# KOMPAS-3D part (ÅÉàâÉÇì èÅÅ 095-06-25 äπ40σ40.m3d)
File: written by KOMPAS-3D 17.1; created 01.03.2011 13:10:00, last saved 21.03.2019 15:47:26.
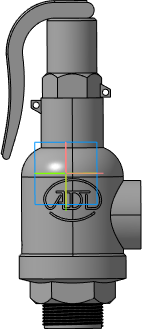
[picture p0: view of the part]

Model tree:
1. Операция без истории:1

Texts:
  Viktor2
